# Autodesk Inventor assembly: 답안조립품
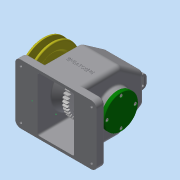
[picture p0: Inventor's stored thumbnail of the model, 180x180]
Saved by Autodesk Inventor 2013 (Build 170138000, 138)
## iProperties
Created: 2016-12
Part Number: 답안조립품
Document SubType Name: Assembly
Designer: Administrator
Author: Administrator
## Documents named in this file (15)
- C:\Users\Administrator\Desktop\461208V1013\답안조립품.iam
- C:\Users\Administrator\Desktop\461208V1013\본체.ipt
- C:\Users\Administrator\Desktop\461208V1013\축.ipt
- C:\Users\Administrator\Desktop\461208V1013\베어링 6203.ipt
- C:\Users\Administrator\Desktop\461208V1013\키 - 6 x 6 x 22.ipt
- C:\Users\Administrator\Desktop\461208V1013\스퍼기어.ipt
- C:\Users\Administrator\Desktop\461208V1013\키 - 5 x 5 x 18.ipt
- C:\Users\Administrator\Desktop\461208V1013\뒤커버.ipt
- C:\Users\Administrator\Desktop\461208V1013\앞커버.ipt
- C:\Users\Administrator\Desktop\461208V1013\오일씰 28 40 8.ipt
- C:\Users\Administrator\Desktop\461208V1013\볼트 M3 x 10.ipt
- C:\Users\Administrator\Desktop\461208V1013\볼트 M3 x 8.ipt
- C:\Users\Administrator\Desktop\461208V1013\V-벨트풀리.ipt
- C:\Users\Administrator\Desktop\461208V1013\멈춤나사 - M4x10.ipt
- C:\Users\Administrator\Desktop\461208V1013\부시.ipt
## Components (9 placed, 3 different names)
1. V-벨트풀리:1
2. ISO 4762 M3 x 10:1
3. ISO 4762 M3 x 10:2
4. ISO 4762 M3 x 10:3
5. ISO 4762 M3 x 10:4
6. ISO 4762 M3 x 8:1
7. ISO 4762 M3 x 8:2
8. ISO 4762 M3 x 8:3
9. ISO 4762 M3 x 8:4
